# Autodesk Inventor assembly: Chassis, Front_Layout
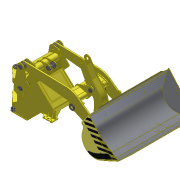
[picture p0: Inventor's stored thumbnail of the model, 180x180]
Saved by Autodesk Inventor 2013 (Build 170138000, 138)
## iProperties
Created: 2005-04
Part Number: Chassis, Front_Layout
Document SubType Name: Assembly
Designer: salex
Manufacturer: Standard
Standards Organization: Custom
Author: salex
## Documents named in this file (6)
- C:\Product Design Suite 2013\Chassis, Front_Layout\Workspace\Chassis, Front_Layout.iam
- C:\Product Design Suite 2013\Chassis, Front_Layout\Workspace\Assy, Chassis, Front\PK46.25.03.000.iam
- C:\Product Design Suite 2013\Chassis, Front_Layout\Workspace\Assy, Chassis, Front\_bucket PK46.80.00.000.iam
- C:\Product Design Suite 2013\Chassis, Front_Layout\Workspace\Parts\MB Hub.ipt
- C:\Product Design Suite 2013\Chassis, Front_Layout\Workspace\Assy, Chassis, Front\PK46.21.01_weldment.iam
- C:\Product Design Suite 2013\Chassis, Front_Layout\Workspace\Assy, Chassis, Front\_boom PK46.25.01.001.iam
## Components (5 placed, 5 different names)
1. PK46.21.01_weldment:1 [sub-assembly] — Mate:1, TBS
2. PK46.25.03.000:1 [sub-assembly] — Mate:21, Mate:25, Mate:26
3. _bucket PK46.80.00.000:1 [sub-assembly] — Mate:19, Mate:20, Mate:21
4. _boom PK46.25.01.001:1 [sub-assembly] — Mate:1, TBS, Mate:19, Mate:20, Mate:23, Flush:1
5. MB Hub:1 — Mate:23, Flush:1, Mate:25, Mate:26
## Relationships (9: Mate 8, Flush 1)
- Mate:1: PK46.21.01_weldment:1 ↔ _boom PK46.25.01.001:1
- TBS [Mate]: PK46.21.01_weldment:1 ↔ _boom PK46.25.01.001:1
- Mate:19: _bucket PK46.80.00.000:1 ↔ _boom PK46.25.01.001:1
- Mate:20: _bucket PK46.80.00.000:1 ↔ _boom PK46.25.01.001:1
- Mate:21: PK46.25.03.000:1 ↔ _bucket PK46.80.00.000:1
- Mate:23: _boom PK46.25.01.001:1 ↔ MB Hub:1
- Flush:1: _boom PK46.25.01.001:1 ↔ MB Hub:1
- Mate:25: PK46.25.03.000:1 ↔ MB Hub:1
- Mate:26: PK46.25.03.000:1 ↔ MB Hub:1
